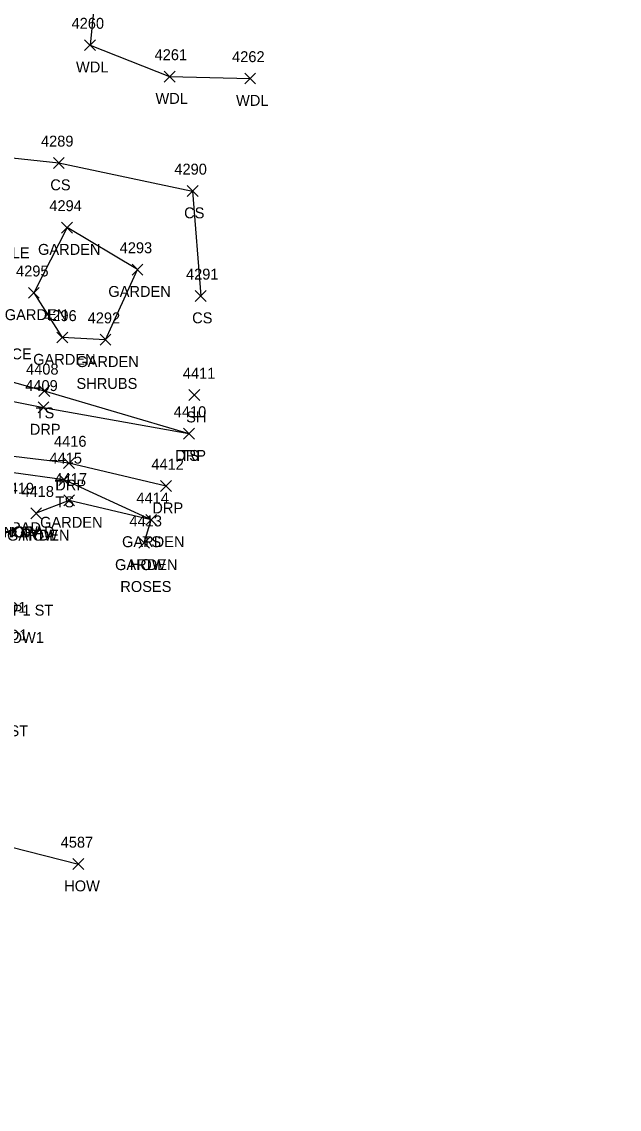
# Model space of a CAD drawing. Extents: x 1443912 to 1445411, y 621446 to 623693.
# Drawn here: x 1444988.1 to 1445097.5, y 623136.5 to 623335.6 of the extents above; entities that cross this region are included whole.
import ezdxf

# ---------------------------------------------------------------- set-up
doc = ezdxf.new("R2010")
doc.units = 0
for name, color, linetype in [('L_A', 7, 'Continuous'), ('L_C', 7, 'Continuous'), ('L_I', 7, 'Continuous'), ('L_TIC', 7, 'Continuous'), ('LAPB', 7, 'Continuous'), ('LAWA', 7, 'Continuous'), ('LBC', 7, 'Continuous'), ('LELB', 7, 'Continuous'), ('R_A', 7, 'Continuous'), ('R_I', 7, 'Continuous'), ('R_TIC', 7, 'Continuous'), ('RDP', 7, 'Continuous')]:
    doc.layers.add(name, color=color, linetype=linetype)

msp = doc.modelspace()

# ---------------------------------------------------------------- linework, layer by layer
at = {"layer": 'L_TIC'}
for points in [[(1444999.64, 623330.28), (1445001.64, 623332.28)], [(1445001.64, 623330.28), (1444999.64, 623332.28)], [(1445014.19, 623324.53), (1445016.19, 623326.53)], [(1445016.19, 623324.53), (1445014.19, 623326.53)], [(1445028.95, 623324.17), (1445030.95, 623326.17)], [(1445030.95, 623324.17), (1445028.95, 623326.17)], [(1444993.92, 623308.71), (1444995.92, 623310.71)], [(1444995.92, 623308.71), (1444993.92, 623310.71)], [(1445018.42, 623303.58), (1445020.42, 623305.58)], [(1445020.42, 623303.58), (1445018.42, 623305.58)], [(1444995.44, 623296.89), (1444997.44, 623298.89)], [(1444997.44, 623296.89), (1444995.44, 623298.89)], [(1445008.32, 623289.19), (1445010.32, 623291.19)], [(1445010.32, 623289.19), (1445008.32, 623291.19)], [(1444989.35, 623284.94), (1444991.35, 623286.94)], [(1444991.35, 623284.94), (1444989.35, 623286.94)], [(1445019.89, 623284.36), (1445021.89, 623286.36)], [(1445021.89, 623284.36), (1445019.89, 623286.36)], [(1444994.55, 623276.76), (1444996.55, 623278.76)], [(1444996.55, 623276.76), (1444994.55, 623278.76)], [(1444994.55, 623276.76), (1444996.55, 623278.76)], [(1444996.55, 623276.76), (1444994.55, 623278.76)], [(1445002.46, 623276.35), (1445004.46, 623278.35)], [(1445004.46, 623276.35), (1445002.46, 623278.35)], [(1445002.46, 623276.35), (1445004.46, 623278.35)], [(1445004.46, 623276.35), (1445002.46, 623278.35)], [(1444991.26, 623266.97), (1444993.26, 623268.97)], [(1444993.26, 623266.97), (1444991.26, 623268.97)], [(1445018.75, 623266.22), (1445020.75, 623268.22)], [(1445020.75, 623266.22), (1445018.75, 623268.22)], [(1445017.74, 623259.17), (1445019.74, 623261.17)], [(1445019.74, 623259.17), (1445017.74, 623261.17)], [(1444994.9, 623250.68), (1444996.9, 623252.68)], [(1444996.9, 623250.68), (1444994.9, 623252.68)], [(1444995.82, 623246.93), (1444997.82, 623248.93)], [(1444997.82, 623246.93), (1444995.82, 623248.93)], [(1444989.77, 623244.58), (1444991.77, 623246.58)], [(1444991.77, 623244.58), (1444989.77, 623246.58)], [(1444989.77, 623244.58), (1444991.77, 623246.58)], [(1444991.77, 623244.58), (1444989.77, 623246.58)], [(1445010.82, 623243.38), (1445012.82, 623245.38)], [(1445012.82, 623243.38), (1445010.82, 623245.38)], [(1445010.82, 623243.38), (1445012.82, 623245.38)], [(1445012.82, 623243.38), (1445010.82, 623245.38)], [(1445009.54, 623239.18), (1445011.54, 623241.18)], [(1445011.54, 623239.18), (1445009.54, 623241.18)], [(1445009.54, 623239.18), (1445011.54, 623241.18)], [(1445011.54, 623239.18), (1445009.54, 623241.18)], [(1444997.51, 623180.37), (1444999.51, 623182.37)], [(1444999.51, 623180.37), (1444997.51, 623182.37)]]:
    msp.add_lwpolyline(points, dxfattribs=at)
at = {"layer": 'LAPB'}
for points in [[(1445003.46, 623277.35), (1445009.32, 623290.19), (1444996.44, 623297.89), (1444990.35, 623285.94), (1444995.55, 623277.76)], [(1445003.46, 623277.35), (1444995.55, 623277.76)], [(1445010.54, 623240.18), (1445011.82, 623244.38), (1444996.82, 623247.93), (1444990.77, 623245.58)]]:
    msp.add_lwpolyline(points, dxfattribs=at)
at = {"layer": 'LAWA'}
msp.add_lwpolyline([(1445040.58, 623347.35), (1445025.95, 623346.18), (1445011.2, 623344.37), (1445001.64, 623341.16), (1445000.64, 623331.28), (1445015.19, 623325.53), (1445029.95, 623325.17)], dxfattribs=at)
at = {"layer": 'LBC'}
msp.add_lwpolyline([(1444979.76, 623186.11), (1444998.51, 623181.37)], dxfattribs=at)
at = {"layer": 'LELB'}
for points in [[(1445097.52, 623539.22), (1445075.7, 623539.93), (1445051.11, 623545.39), (1445040.13, 623540.27), (1445036.37, 623522.01), (1445021.48, 623458.8), (1445005.96, 623403.97), (1444993.72, 623362.86), (1444977.79, 623311.56), (1444964.52, 623276.17), (1444977.62, 623272.11), (1444992.26, 623267.97), (1445018.74, 623260.17)], [(1444977.79, 623311.56), (1444994.92, 623309.71), (1445019.42, 623304.58), (1445020.89, 623285.36)], [(1445011.82, 623244.38), (1444995.9, 623251.68), (1444976.44, 623254.41), (1444961.7, 623251.97), (1444954.05, 623221.94), (1444942.83, 623181.55), (1444935.09, 623155.08), (1444941.3, 623148.68), (1444957.21, 623141.48), (1444982.16, 623136.48)]]:
    msp.add_lwpolyline(points, dxfattribs=at)
at = {"layer": 'R_TIC'}
for points in [[(1444991.11, 623263.96), (1444993.11, 623265.96)], [(1444993.11, 623263.96), (1444991.11, 623265.96)], [(1445017.74, 623259.17), (1445019.74, 623261.17)], [(1445019.74, 623259.17), (1445017.74, 623261.17)], [(1444995.78, 623253.76), (1444997.78, 623255.76)], [(1444997.78, 623253.76), (1444995.78, 623255.76)], [(1445013.55, 623249.56), (1445015.55, 623251.56)], [(1445015.55, 623249.56), (1445013.55, 623251.56)]]:
    msp.add_lwpolyline(points, dxfattribs=at)
at = {"layer": 'RDP'}
for points in [[(1444959.91, 623275.87), (1444965.39, 623272.23), (1444976.71, 623268.01), (1444992.11, 623264.96), (1445018.74, 623260.17)], [(1445014.55, 623250.56), (1444996.78, 623254.76), (1444980, 623256.76), (1444962.2, 623259.54), (1444955.54, 623257.94)]]:
    msp.add_lwpolyline(points, dxfattribs=at)

# ---------------------------------------------------------------- texts
at = {"layer": 'L_A'}
for s, p in [('WDL', (1444998.06, 623326.28)), ('WDL', (1445012.61, 623320.53)), ('WDL', (1445027.36, 623320.17)), ('CS', (1444993.36, 623304.71)), ('CS', (1445017.86, 623299.58)), ('GARDEN', (1444991.11, 623292.89)), ('GARDEN', (1445003.98, 623285.19)), ('GARDEN', (1444985.02, 623280.94)), ('CS', (1445019.33, 623280.36)), ('GARDEN', (1444990.22, 623272.76)), ('GARDEN', (1444990.22, 623272.76)), ('GARDEN', (1444998.12, 623272.35)), ('GARDEN', (1444998.12, 623272.35)), ('TS', (1444990.67, 623262.97)), ('SH', (1445018.23, 623262.22)), ('TS', (1445017.15, 623255.17)), ('TS', (1444994.31, 623246.68)), ('CONCPAD', (1444978.28, 623241.95)), ('GARDEN', (1444991.49, 623242.93)), ('CONCPAD', (1444980.78, 623241.17)), ('HOW', (1444984.52, 623241.17)), ('GARDEN', (1444985.44, 623240.58)), ('HOW', (1444988.16, 623240.58)), ('GARDEN', (1445006.49, 623239.38)), ('TS', (1445010.23, 623239.38)), ('GARDEN', (1445005.21, 623235.18)), ('HOW', (1445007.93, 623235.18)), ('HOW1 STP1 ST', (1444974.29, 623226.85)), ('STP1 CPD1', (1444974.43, 623227.37)), ('STPW1 CPD1', (1444972.08, 623222.31)), ('STPW1 HOW1', (1444974.21, 623221.84)), ('POR1 STPW1 ST', (1444967.9, 623204.77)), ('HOW', (1444995.9, 623176.37))]:
    msp.add_text(s, height=2, dxfattribs=at).set_placement(p)
at = {"layer": 'L_C'}
for s, p in [('M.APPLE', (1444977.99, 623292.26)), ('M.BSPRUCE', (1444974.06, 623273.76)), ('SHRUBS', (1444998.15, 623268.35)), ('SHRUBS', (1444998.15, 623268.35)), ('ROSES', (1445006.17, 623231.18))]:
    msp.add_text(s, height=2, dxfattribs=at).set_placement(p)
at = {"layer": 'L_I'}
for s, p in [('4260', (1444997.25, 623334.28)), ('4261', (1445012.45, 623328.53)), ('4262', (1445026.64, 623328.17)), ('4289', (1444991.65, 623312.71)), ('4290', (1445016.07, 623307.58)), ('4294', (1444993.18, 623300.89)), ('4293', (1445006.06, 623293.19)), ('4295', (1444987.09, 623288.94)), ('4291', (1445018.2, 623288.36)), ('4296', (1444992.24, 623280.76)), ('4296', (1444992.24, 623280.76)), ('4292', (1445000.2, 623280.35)), ('4292', (1445000.2, 623280.35)), ('4408', (1444988.92, 623270.97)), ('4411', (1445017.62, 623270.22)), ('4410', (1445015.96, 623263.17)), ('4415', (1444993.21, 623254.68)), ('4417', (1444994.13, 623250.93)), ('4419', (1444984.43, 623249.17)), ('4419', (1444984.43, 623249.17)), ('4418', (1444988.08, 623248.58)), ('4418', (1444988.08, 623248.58)), ('4414', (1445009.13, 623247.38)), ('4414', (1445009.13, 623247.38)), ('4413', (1445007.85, 623243.18)), ('4413', (1445007.85, 623243.18)), ('4587', (1444995.26, 623184.37))]:
    msp.add_text(s, height=2, dxfattribs=at).set_placement(p)
at = {"layer": 'R_A'}
for p in [(1444989.6, 623259.96), (1445016.22, 623255.17), (1444994.27, 623249.76), (1445012.04, 623245.56)]:
    msp.add_text('DRP', height=2, dxfattribs=at).set_placement(p)
at = {"layer": 'R_I'}
for s, p in [('4409', (1444988.77, 623267.96)), ('4410', (1445015.96, 623263.17)), ('4416', (1444994.04, 623257.76)), ('4412', (1445011.86, 623253.56))]:
    msp.add_text(s, height=2, dxfattribs=at).set_placement(p)

doc.saveas('drawing.dxf')
